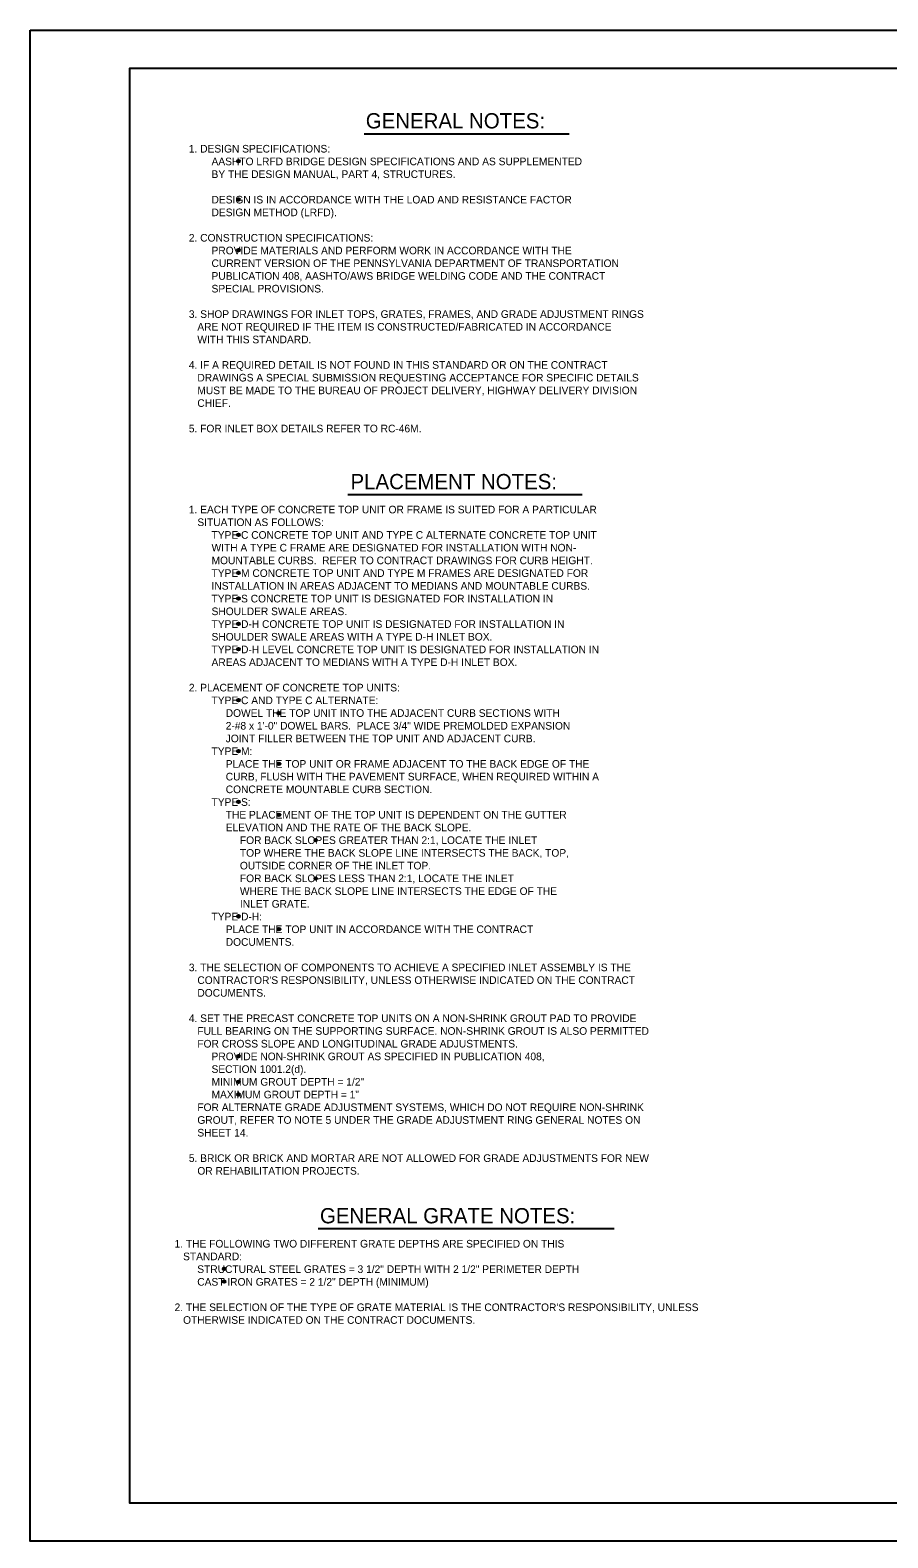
# Model space of a CAD drawing. Extents: x 2087776 to 2104538, y 970919 to 982612.
# Drawn here: x 2090535 to 2091640, y 980668 to 982612 of the extents above; entities that cross this region are included whole.
import ezdxf

# ---------------------------------------------------------------- set-up
doc = ezdxf.new("R2010")
doc.units = 0
doc.layers.add('1', color=7, linetype='Continuous')
doc.layers.add('PLT-BNDY', color=7, linetype='Continuous')

msp = doc.modelspace()

# ---------------------------------------------------------------- linework, layer by layer
at = {"layer": '1'}
for p, q in [((2090965.6, 982478.7), (2091229.5, 982478.7)), ((2090944.4, 982013.3), (2091246.4, 982013.3)), ((2090905.9, 981066.4), (2091287.7, 981066.4))]:
    msp.add_line(p, q, dxfattribs=at)
msp.add_lwpolyline([(2093241.6, 980712.6), (2093241.6, 982563), (2090662.8, 982563), (2090662.8, 980712.6), (2093241.6, 980712.6), (2093241.6, 980799.1), (2092585.4, 980799.1), (2092585.4, 981011.3), (2093241.6, 981011.3), (2093241.6, 981106.3), (2092585.4, 981106.3), (2092585.4, 980712.6), (2092843.9, 980712.6), (2092843.9, 980799.1), (2092843.9, 980712.6), (2093096.5, 980712.6), (2093096.5, 980799.1), (2093096.5, 980758.7), (2093241.6, 980758.7)], dxfattribs=at)
for centre, radius in [((2090803.5, 982443.2), 1.75), ((2090803.5, 982443.2), 1.31), ((2090803.5, 982443.2), 0.875), ((2090803.5, 982443.2), 0.437), ((2090803.5, 982394), 1.75), ((2090803.5, 982394), 1.31), ((2090803.5, 982394), 0.875), ((2090803.5, 982394), 0.437), ((2090803.5, 982328.4), 1.75), ((2090803.5, 982328.4), 1.31), ((2090803.5, 982328.4), 0.875), ((2090803.5, 982328.4), 0.437), ((2090803.5, 981961.3), 1.75), ((2090803.5, 981961.3), 1.31), ((2090803.5, 981961.3), 0.875), ((2090803.5, 981961.3), 0.437), ((2090803.5, 981912.1), 1.75), ((2090803.5, 981912.1), 1.31), ((2090803.5, 981912.1), 0.875), ((2090803.5, 981912.1), 0.437), ((2090803.5, 981879.3), 1.75), ((2090803.5, 981879.3), 1.31), ((2090803.5, 981879.3), 0.875), ((2090803.5, 981879.3), 0.437), ((2090803.5, 981846.5), 1.75), ((2090803.5, 981846.5), 1.31), ((2090803.5, 981846.5), 0.875), ((2090803.5, 981846.5), 0.437), ((2090803.5, 981813.7), 1.75), ((2090803.5, 981813.7), 1.31), ((2090803.5, 981813.7), 0.875), ((2090803.5, 981813.7), 0.437), ((2090803.5, 981748), 1.75), ((2090803.5, 981748), 1.31), ((2090803.5, 981748), 0.875), ((2090803.5, 981748), 0.437), ((2090855.4, 981731.4), 1.75), ((2090855.4, 981731.4), 1.31), ((2090855.4, 981731.4), 0.875), ((2090855.4, 981731.4), 0.437), ((2090803.5, 981682.4), 1.75), ((2090803.5, 981682.4), 1.31), ((2090803.5, 981682.4), 0.875), ((2090803.5, 981682.4), 0.437), ((2090855.4, 981665.8), 1.75), ((2090855.4, 981665.8), 1.31), ((2090855.4, 981665.8), 0.875), ((2090855.4, 981665.8), 0.437), ((2090803.5, 981616.8), 1.75), ((2090803.5, 981616.8), 1.31), ((2090803.5, 981616.8), 0.875), ((2090803.5, 981616.8), 0.437), ((2090855.4, 981600.1), 1.75), ((2090855.4, 981600.1), 1.31), ((2090855.4, 981600.1), 0.875), ((2090855.4, 981600.1), 0.437), ((2090902.9, 981567.3), 1.75), ((2090902.9, 981567.3), 1.31), ((2090902.9, 981567.3), 0.875), ((2090902.9, 981567.3), 0.437), ((2090902.9, 981518.1), 1.75), ((2090902.9, 981518.1), 1.31), ((2090902.9, 981518.1), 0.875), ((2090902.9, 981518.1), 0.437), ((2090803.5, 981469.2), 1.75), ((2090803.5, 981469.2), 1.31), ((2090803.5, 981469.2), 0.875), ((2090803.5, 981469.2), 0.437), ((2090855.4, 981452.5), 1.75), ((2090855.4, 981452.5), 1.31), ((2090855.4, 981452.5), 0.875), ((2090855.4, 981452.5), 0.437), ((2090803.5, 981288.7), 1.75), ((2090803.5, 981288.7), 1.31), ((2090803.5, 981288.7), 0.875), ((2090803.5, 981288.7), 0.437), ((2090803.5, 981255.9), 1.75), ((2090803.5, 981255.9), 1.31), ((2090803.5, 981255.9), 0.875), ((2090803.5, 981255.9), 0.437), ((2090803.5, 981239.5), 1.75), ((2090803.5, 981239.5), 1.31), ((2090803.5, 981239.5), 0.875), ((2090803.5, 981239.5), 0.437), ((2090785, 981014.4), 1.75), ((2090785, 981014.4), 1.31), ((2090785, 981014.4), 0.875), ((2090785, 981014.4), 0.437), ((2090785, 980998), 1.75), ((2090785, 980998), 1.31), ((2090785, 980998), 0.875), ((2090785, 980998), 0.437)]:
    msp.add_circle(centre, radius, dxfattribs=at)
at = {"layer": 'PLT-BNDY'}
msp.add_lwpolyline([(2090534.9, 982612.3), (2093294, 982612.3), (2093294, 980663.4), (2090534.9, 980663.4)], close=True, dxfattribs=at)

# ---------------------------------------------------------------- texts
at = {"layer": '1'}
for s, height, p in [('GENERAL NOTES:', 19.685, (2090967.5, 982485.5)), ('1. DESIGN SPECIFICATIONS:', 9.843, (2090739.4, 982454.4)), ('        AASHTO LRFD BRIDGE DESIGN SPECIFICATIONS AND AS SUPPLEMENTED ', 9.843, (2090739.4, 982438)), ('        BY THE DESIGN MANUAL, PART 4, STRUCTURES.', 9.843, (2090739.4, 982421.6)), ('        DESIGN IS IN ACCORDANCE WITH THE LOAD AND RESISTANCE FACTOR', 9.843, (2090739.4, 982388.7)), ('        DESIGN METHOD (LRFD).', 9.843, (2090739.4, 982372.3)), ('2. CONSTRUCTION SPECIFICATIONS:', 9.843, (2090739.4, 982339.5)), ('        CURRENT VERSION OF THE PENNSYLVANIA DEPARTMENT OF TRANSPORTATION', 9.843, (2090739.4, 982306.7)), ('        PROVIDE MATERIALS AND PERFORM WORK IN ACCORDANCE WITH THE', 9.843, (2090739.4, 982323.1)), ('        PUBLICATION 408, AASHTO/AWS BRIDGE WELDING CODE AND THE CONTRACT', 9.843, (2090739.4, 982290.3)), ('        SPECIAL PROVISIONS.', 9.843, (2090739.4, 982273.9)), ('3. SHOP DRAWINGS FOR INLET TOPS, GRATES, FRAMES, AND GRADE ADJUSTMENT RINGS', 9.843, (2090739.4, 982241.1)), ('   ARE NOT REQUIRED IF THE ITEM IS CONSTRUCTED/FABRICATED IN ACCORDANCE', 9.843, (2090739.4, 982224.7)), ('   WITH THIS STANDARD.', 9.843, (2090739.4, 982208.3)), ('4. IF A REQUIRED DETAIL IS NOT FOUND IN THIS STANDARD OR ON THE CONTRACT', 9.843, (2090739.4, 982175.5)), ('   DRAWINGS A SPECIAL SUBMISSION REQUESTING ACCEPTANCE FOR SPECIFIC DETAILS', 9.843, (2090739.4, 982159.1)), ('   MUST BE MADE TO THE BUREAU OF PROJECT DELIVERY, HIGHWAY DELIVERY DIVISION', 9.843, (2090739.4, 982142.7)), ('   CHIEF.', 9.84, (2090739.4, 982126.3)), ('5. FOR INLET BOX DETAILS REFER TO RC-46M.', 9.843, (2090739.4, 982093.5)), ('PLACEMENT NOTES:', 19.685, (2090947.8, 982020.1)), ('1. EACH TYPE OF CONCRETE TOP UNIT OR FRAME IS SUITED FOR A PARTICULAR', 9.843, (2090739.4, 981989)), ('   SITUATION AS FOLLOWS:', 9.843, (2090739.4, 981972.6)), ('        TYPE C CONCRETE TOP UNIT AND TYPE C ALTERNATE CONCRETE TOP UNIT', 9.843, (2090739.4, 981956.2)), ('        WITH A TYPE C FRAME ARE DESIGNATED FOR INSTALLATION WITH NON-', 9.843, (2090739.4, 981939.8)), ('        MOUNTABLE CURBS.  REFER TO CONTRACT DRAWINGS FOR CURB HEIGHT.', 9.843, (2090739.4, 981923.4)), ('        TYPE M CONCRETE TOP UNIT AND TYPE M FRAMES ARE DESIGNATED FOR', 9.843, (2090739.4, 981907)), ('        INSTALLATION IN AREAS ADJACENT TO MEDIANS AND MOUNTABLE CURBS.', 9.843, (2090739.4, 981890.5)), ('        TYPE S CONCRETE TOP UNIT IS DESIGNATED FOR INSTALLATION IN', 9.843, (2090739.4, 981874.1)), ('        TYPE D-H CONCRETE TOP UNIT IS DESIGNATED FOR INSTALLATION IN', 9.843, (2090739.4, 981841.3)), ('        SHOULDER SWALE AREAS.', 9.843, (2090739.4, 981857.7)), ('        SHOULDER SWALE AREAS WITH A TYPE D-H INLET BOX.', 9.843, (2090739.4, 981824.9)), ('        TYPE D-H LEVEL CONCRETE TOP UNIT IS DESIGNATED FOR INSTALLATION IN', 9.843, (2090739.4, 981808.5)), ('        AREAS ADJACENT TO MEDIANS WITH A TYPE D-H INLET BOX.', 9.843, (2090739.4, 981792.1)), ('2. PLACEMENT OF CONCRETE TOP UNITS:', 9.843, (2090739.4, 981759.3)), ('        TYPE C AND TYPE C ALTERNATE:', 9.843, (2090739.4, 981742.9)), ('             DOWEL THE TOP UNIT INTO THE ADJACENT CURB SECTIONS WITH', 9.843, (2090739.4, 981726.5)), ('             2-#8 x 1\'-0" DOWEL BARS.  PLACE 3/4" WIDE PREMOLDED EXPANSION', 9.843, (2090739.4, 981710.1)), ('             JOINT FILLER BETWEEN THE TOP UNIT AND ADJACENT CURB.', 9.843, (2090739.4, 981693.7)), ('        TYPE M:', 9.843, (2090739.4, 981677.3)), ('             PLACE THE TOP UNIT OR FRAME ADJACENT TO THE BACK EDGE OF THE', 9.843, (2090739.4, 981660.9)), ('             CURB, FLUSH WITH THE PAVEMENT SURFACE, WHEN REQUIRED WITHIN A', 9.843, (2090739.4, 981644.5)), ('             CONCRETE MOUNTABLE CURB SECTION.', 9.843, (2090739.4, 981628.1)), ('        TYPE S:', 9.843, (2090739.4, 981611.7)), ('             THE PLACEMENT OF THE TOP UNIT IS DEPENDENT ON THE GUTTER', 9.843, (2090739.4, 981595.3)), ('             ELEVATION AND THE RATE OF THE BACK SLOPE.', 9.843, (2090739.4, 981578.9)), ('                  FOR BACK SLOPES GREATER THAN 2:1, LOCATE THE INLET', 9.843, (2090739.4, 981562.5)), ('                  TOP WHERE THE BACK SLOPE LINE INTERSECTS THE BACK, TOP,', 9.843, (2090739.4, 981546.1)), ('                  OUTSIDE CORNER OF THE INLET TOP.', 9.843, (2090739.4, 981529.7)), ('                  FOR BACK SLOPES LESS THAN 2:1, LOCATE THE INLET', 9.843, (2090739.4, 981513.3)), ('                  WHERE THE BACK SLOPE LINE INTERSECTS THE EDGE OF THE', 9.843, (2090739.4, 981496.8)), ('                  INLET GRATE.', 9.843, (2090739.4, 981480.4)), ('        TYPE D-H:', 9.843, (2090739.4, 981464)), ('             PLACE THE TOP UNIT IN ACCORDANCE WITH THE CONTRACT', 9.843, (2090739.4, 981447.6)), ('             DOCUMENTS.', 9.843, (2090739.4, 981431.2)), ('3. THE SELECTION OF COMPONENTS TO ACHIEVE A SPECIFIED INLET ASSEMBLY IS THE', 9.843, (2090739.4, 981398.4)), ("   CONTRACTOR'S RESPONSIBILITY, UNLESS OTHERWISE INDICATED ON THE CONTRACT", 9.843, (2090739.4, 981382)), ('   DOCUMENTS.', 9.843, (2090739.4, 981365.6)), ('4. SET THE PRECAST CONCRETE TOP UNITS ON A NON-SHRINK GROUT PAD TO PROVIDE', 9.843, (2090739.4, 981332.8)), ('   FULL BEARING ON THE SUPPORTING SURFACE. NON-SHRINK GROUT IS ALSO PERMITTED', 9.843, (2090739.4, 981316.4)), ('   FOR CROSS SLOPE AND LONGITUDINAL GRADE ADJUSTMENTS.', 9.843, (2090739.4, 981300)), ('        PROVIDE NON-SHRINK GROUT AS SPECIFIED IN PUBLICATION 408,', 9.843, (2090739.4, 981283.6)), ('        SECTION 1001.2(d).', 9.843, (2090739.4, 981267.2)), ('        MINIMUM GROUT DEPTH = 1/2"', 9.843, (2090739.4, 981250.8)), ('   FOR ALTERNATE GRADE ADJUSTMENT SYSTEMS, WHICH DO NOT REQUIRE NON-SHRINK', 9.843, (2090739.4, 981218)), ('        MAXIMUM GROUT DEPTH = 1"', 9.843, (2090739.4, 981234.4)), ('   GROUT, REFER TO NOTE 5 UNDER THE GRADE ADJUSTMENT RING GENERAL NOTES ON', 9.843, (2090739.4, 981201.6)), ('   SHEET 14.    ', 9.843, (2090739.4, 981185.2)), ('5. BRICK OR BRICK AND MORTAR ARE NOT ALLOWED FOR GRADE ADJUSTMENTS FOR NEW', 9.843, (2090739.4, 981152.4)), ('   OR REHABILITATION PROJECTS.', 9.843, (2090739.4, 981136)), ('GENERAL GRATE NOTES:', 19.685, (2090908.4, 981073.2)), ('1. THE FOLLOWING TWO DIFFERENT GRATE DEPTHS ARE SPECIFIED ON THIS', 9.843, (2090721, 981042)), ('   STANDARD:', 9.843, (2090721, 981025.6)), ('        STRUCTURAL STEEL GRATES = 3 1/2" DEPTH WITH 2 1/2" PERIMETER DEPTH', 9.843, (2090721, 981009.2)), ('        CAST IRON GRATES = 2 1/2" DEPTH (MINIMUM)', 9.843, (2090721, 980992.8)), ("2. THE SELECTION OF THE TYPE OF GRATE MATERIAL IS THE CONTRACTOR'S RESPONSIBILITY, UNLESS", 9.843, (2090721, 980960)), ('   OTHERWISE INDICATED ON THE CONTRACT DOCUMENTS.', 9.843, (2090721, 980943.6))]:
    msp.add_text(s, height=height, dxfattribs=at).set_placement(p)

doc.saveas('drawing.dxf')
